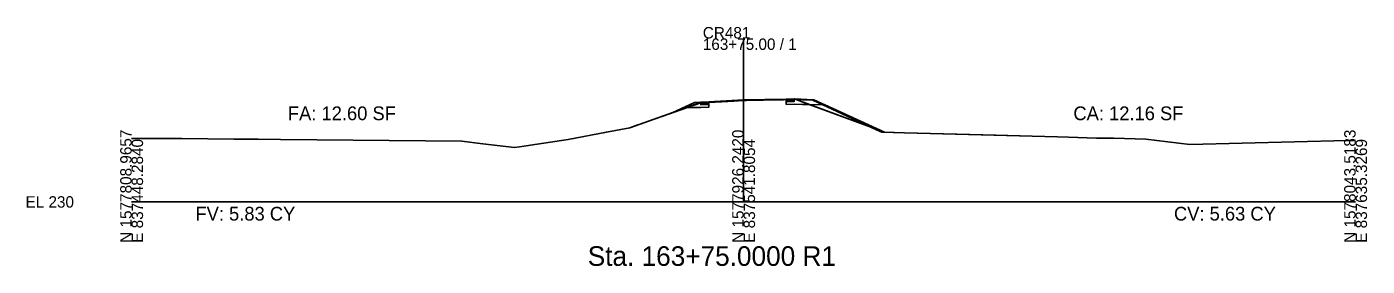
# Model space of a CAD drawing. Extents: x -26 to 303, y -16 to 6048.
# Drawn here: x -25.7 to 302.8, y 484.3 to 542.8 of the extents above; entities that cross this region are included whole.
import ezdxf

# ---------------------------------------------------------------- set-up
doc = ezdxf.new("R2010")
doc.units = 0
for name, color, linetype in [('ASPHALT_19MM1', 7, 'Continuous'), ('ASPHALT_9_5MM1', 7, 'Continuous'), ('Draft_XS_Grid', 7, 'Continuous'), ('Draft_XS_Text', 7, 'Continuous'), ('DTM_P_FINISHED_GRADE2', 7, 'Continuous'), ('DTM_TEMP_DROP', 7, 'Continuous'), ('DTM_X_GROUND', 7, 'Continuous'), ('TRANS_PAVED_SHOULDERS', 7, 'Continuous'), ('XS_CELL', 7, 'Continuous'), ('XS_M_SHAPES_EARTHWORK', 7, 'Continuous'), ('XS_P_ASPHALT', 7, 'Continuous'), ('XS_P_GROUND', 7, 'Continuous'), ('XS_P_NULL_POINT', 7, 'Continuous'), ('XS_P_SHOULDER', 7, 'Continuous'), ('XS_P_SUBGRADE_GRANULAR', 7, 'Continuous'), ('XS_P_SUBGRADE_LEVELING', 7, 'Continuous'), ('XS_P_SUBGRADE_MILLING', 7, 'Continuous'), ('XS_SHEET_EW_TX_AREA', 7, 'Continuous'), ('XS_SHEET_EW_TX_VOLUME', 7, 'Continuous')]:
    doc.layers.add(name, color=color, linetype=linetype)

msp = doc.modelspace()

# ---------------------------------------------------------------- linework, layer by layer
at = {"layer": 'ASPHALT_19MM1'}
for points in [[(141.49, 524.15), (141.49, 523.88), (139.49, 523.78), (139.49, 524.05), (141.49, 524.15)], [(160.43, 524.82), (160.43, 524.55), (162.43, 524.59), (162.43, 524.86), (160.43, 524.82)]]:
    msp.add_lwpolyline(points, dxfattribs=at)
at = {"layer": 'ASPHALT_9_5MM1'}
for points in [[(141.49, 524.49), (141.49, 524.36), (139.49, 524.26), (139.49, 524.38), (141.49, 524.49)], [(160.43, 525.15), (160.43, 525.03), (162.43, 525.07), (162.43, 525.19), (160.43, 525.15)]]:
    msp.add_lwpolyline(points, dxfattribs=at)
at = {"layer": 'DTM_P_FINISHED_GRADE2'}
msp.add_lwpolyline([(132.66, 521.86), (132.66, 521.86), (137.99, 524.3), (139.49, 524.38), (141.49, 524.49), (150, 524.95), (160.43, 525.15), (162.43, 525.19), (167.21, 525), (184.56, 517.05)], dxfattribs=at)
at = {"layer": 'DTM_X_GROUND'}
for points in [[(0, 515.51), (12.32, 515.48), (25.03, 515.39), (30.98, 515.33), (36.48, 515.28), (80.92, 514.85), (86.07, 514.23), (93.81, 513.29), (95.05, 513.47), (107.01, 515.28), (116.39, 517.08), (122.08, 518.16), (124.07, 518.86), (124.61, 519.05), (126.68, 519.77), (132.66, 521.86), (132.66, 521.86), (139.49, 524.38), (141.49, 524.49), (141.49, 524.49), (150, 524.95), (150, 524.95), (160.43, 525.15), (160.43, 525.15), (162.43, 525.19), (162.43, 525.19), (184.56, 517.05), (184.56, 517.05), (184.56, 517.05), (189.46, 516.92), (211.79, 516.33), (220.75, 516.09), (226.94, 515.93), (229.59, 515.86), (236.51, 515.57), (240.71, 515.59), (248.61, 515.37), (259.33, 514.04), (297.85, 515), (300, 515.06)], [(0, 515.51), (12.32, 515.48), (25.03, 515.39), (30.98, 515.33), (36.48, 515.28), (80.92, 514.85), (86.07, 514.23), (93.81, 513.29), (95.05, 513.47), (107.01, 515.28), (116.39, 517.08), (122.08, 518.16), (126.68, 519.78), (139.49, 524.23), (144.67, 524.52), (150.7, 524.88), (157.57, 525.03), (162.43, 525.14), (164.41, 525.02), (166.93, 524.88), (182.58, 517.68), (183.91, 517.07), (189.46, 516.92), (220.75, 516.09), (226.94, 515.93), (229.59, 515.86), (236.51, 515.57), (240.71, 515.59), (248.61, 515.37), (259.33, 514.04), (297.85, 515), (300, 515.06)]]:
    msp.add_lwpolyline(points, dxfattribs=at)
at = {"layer": 'TRANS_PAVED_SHOULDERS'}
for points in [[(141.49, 524.36), (141.49, 524.15), (139.49, 524.05), (139.49, 524.26), (141.49, 524.36)], [(160.43, 525.03), (160.43, 524.82), (162.43, 524.86), (162.43, 525.07), (160.43, 525.03)]]:
    msp.add_lwpolyline(points, dxfattribs=at)
at = {"layer": 'XS_CELL'}
for p, q in [((150, 500), (150, 540)), ((0, 500), (150, 500)), ((150, 500), (300, 500))]:
    msp.add_line(p, q, dxfattribs=at)
at = {"layer": 'XS_M_SHAPES_EARTHWORK'}
for points in [[(132.66, 521.86), (135.86, 523.04), (135.21, 523.02)], [(135.86, 523.04), (139.49, 524.38), (141.49, 524.49), (150, 524.95), (160.43, 525.15), (162.43, 525.19), (166.08, 523.85), (164.43, 523.88), (162.43, 523.92), (160.43, 523.88), (160.43, 524.55), (160.43, 524.82), (160.43, 525.03), (159.8, 525.01), (150, 524.82), (147.58, 524.69), (144.67, 524.52), (141.49, 524.34), (141.49, 524.15), (141.49, 523.88), (141.49, 523.22), (139.49, 523.11), (137.49, 523.07)], [(166.08, 523.85), (184.56, 517.05), (169.89, 523.77)]]:
    msp.add_lwpolyline(points, close=True, dxfattribs=at)
at = {"layer": 'XS_P_ASPHALT'}
msp.add_lwpolyline([(141.49, 524.49), (141.49, 524.36), (150, 524.82), (150, 524.82), (160.43, 525.03), (160.43, 525.03), (160.43, 525.15), (160.43, 525.15), (160.43, 525.15), (150, 524.95), (150, 524.95), (141.49, 524.49), (141.49, 524.49)], dxfattribs=at)
at = {"layer": 'XS_P_GROUND'}
for points in [[(132.66, 521.86), (132.66, 521.86), (137.99, 524.3)], [(184.56, 517.05), (184.56, 517.05), (167.21, 525)]]:
    msp.add_lwpolyline(points, dxfattribs=at)
at = {"layer": 'XS_P_SHOULDER'}
for points in [[(139.49, 524.38), (137.99, 524.3)], [(162.43, 525.19), (167.21, 525)]]:
    msp.add_lwpolyline(points, dxfattribs=at)
at = {"layer": 'XS_P_SUBGRADE_GRANULAR'}
for points in [[(139.49, 523.11), (137.49, 523.07), (135.21, 523.02)], [(141.49, 523.22), (139.49, 523.11)], [(141.49, 523.22), (141.49, 524.49)], [(160.43, 523.88), (160.43, 525.15)], [(160.43, 523.88), (162.43, 523.92)], [(162.43, 523.92), (164.43, 523.88), (169.89, 523.77)]]:
    msp.add_lwpolyline(points, dxfattribs=at)
at = {"layer": 'XS_P_SUBGRADE_LEVELING'}
msp.add_lwpolyline([(160.43, 525.03), (157.57, 524.97), (157.57, 524.97), (150.7, 524.84), (150.7, 524.84), (150.7, 524.84), (150, 524.82), (150, 524.82), (144.67, 524.53), (144.67, 524.53), (141.49, 524.36), (141.49, 524.36), (141.49, 524.34), (144.67, 524.52), (144.67, 524.52), (147.58, 524.69), (147.58, 524.69), (150, 524.82), (150, 524.82), (150.7, 524.84), (150.7, 524.84), (150.7, 524.84), (157.57, 524.97), (157.57, 524.97), (160.43, 525.03)], dxfattribs=at)
at = {"layer": 'XS_P_SUBGRADE_MILLING'}
msp.add_lwpolyline([(141.49, 524.34), (144.67, 524.52), (144.67, 524.52), (147.58, 524.69), (147.58, 524.69), (150, 524.82), (150, 524.82), (150.7, 524.84), (150.7, 524.84), (150.7, 524.84), (157.57, 524.97), (157.57, 524.97), (160.43, 525.03), (160.43, 525.09), (157.57, 525.03), (157.57, 525.03), (150.7, 524.88), (150.7, 524.88), (150.7, 524.88), (150, 524.83), (150, 524.83), (144.67, 524.52), (144.67, 524.52), (141.49, 524.34)], dxfattribs=at)

# ---------------------------------------------------------------- texts
at = {"layer": 'Draft_XS_Grid'}
msp.add_text('-', height=0.0001, dxfattribs=at).set_placement((0, 500))
at = {"layer": 'Draft_XS_Text'}
msp.add_text('Sta. 163+75.0000 R1', height=4.8, dxfattribs=at).set_placement((111.79, 484.35))
at = {"layer": 'DTM_TEMP_DROP'}
for p in [(132.59, 521.74), (184.48, 516.93)]:
    msp.add_text('X', height=0.24, dxfattribs=at).set_placement(p)
at = {"layer": 'XS_CELL'}
for s, p in [('CR481', (140, 540)), ('163+75.00 / 1', (140, 537.2)), ('EL 230', (-26, 498.6))]:
    msp.add_text(s, height=2.8, dxfattribs=at).set_placement(p)
for s, p in [('N 1577808.9657', (0, 490)), ('N 1577926.2420', (150, 490)), ('N 1578043.5183', (300, 490)), ('E 837448.2840', (2.8, 490)), ('E 837541.8054', (152.8, 490)), ('E 837635.3269', (302.8, 490))]:
    msp.add_text(s, height=2.8, rotation=90, dxfattribs=at).set_placement(p)
at = {"layer": 'XS_P_GROUND'}
for p in [(137.91, 524.18), (167.13, 524.88)]:
    msp.add_text('X', height=0.24, dxfattribs=at).set_placement(p)
at = {"layer": 'XS_P_NULL_POINT'}
for p in [(139.41, 524.26), (141.41, 524.37), (149.92, 524.83), (160.35, 525.03), (162.35, 525.07)]:
    msp.add_text('X', height=0.24, dxfattribs=at).set_placement(p)
at = {"layer": 'XS_P_SUBGRADE_GRANULAR'}
for p in [(132.59, 521.74), (184.48, 516.93)]:
    msp.add_text('X', height=0.24, dxfattribs=at).set_placement(p)
at = {"layer": 'XS_SHEET_EW_TX_AREA'}
for s, p in [('FA: 12.60 SF', (38.3, 520)), ('CA: 12.16 SF', (230.83, 520))]:
    msp.add_text(s, height=3.36, dxfattribs=at).set_placement(p)
at = {"layer": 'XS_SHEET_EW_TX_VOLUME'}
for s, p in [('FV: 5.83 CY', (15.64, 495.44)), ('CV: 5.63 CY', (255.48, 495.44))]:
    msp.add_text(s, height=3.36, dxfattribs=at).set_placement(p)

doc.saveas('drawing.dxf')
